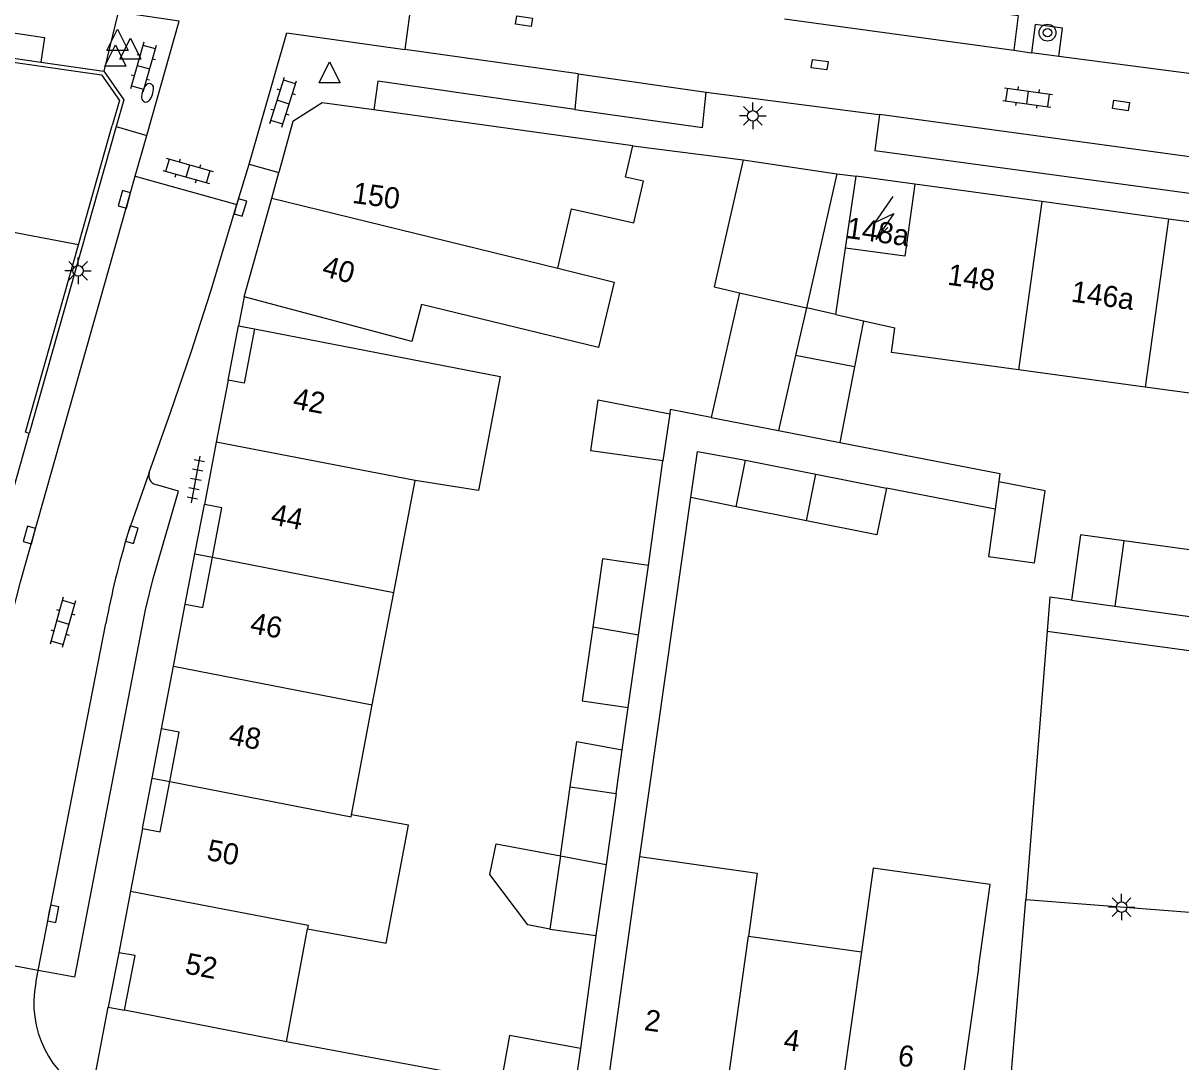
# Model space of a CAD drawing. Extents: x 132998 to 136004, y 396998 to 398512.
# Drawn here: x 133682.3 to 133737.1, y 397708.1 to 397757.2 of the extents above; entities that cross this region are included whole.
import ezdxf

# ---------------------------------------------------------------- set-up
doc = ezdxf.new("R2010")
doc.units = 0
for name, color, linetype in [('gg-afsc-erfafscheiding', 7, 'Continuous'), ('gg-afsc-muur', 7, 'Continuous'), ('gg-anno-huisnummerreeks BGT', 7, 'Continuous'), ('gg-bbg-bijgebouw', 7, 'Continuous'), ('gg-bbg-gedigitaliseerde bebouwing', 7, 'Continuous'), ('gg-bbg-gedigitaliseerde bijgebouw', 7, 'Continuous'), ('gg-bbg-hoofdgebouw', 7, 'Continuous'), ('gg-bbg-luifel en loopbrug', 7, 'Continuous'), ('gg-bbg-onder overbouw', 7, 'Continuous'), ('gg-bbg-pand overbouw', 7, 'Continuous'), ('gg-bbg-tussenscheiding', 7, 'Continuous'), ('gg-bbg-tussenscheiding niveau 01', 7, 'Continuous'), ('gg-knt-verharding', 7, 'Continuous'), ('gg-knt-verharding nz', 7, 'Continuous'), ('gt-grn-vlakafsluiter', 7, 'Continuous'), ('gt-grn-weggrens', 7, 'Continuous'), ('gt-symb-boom', 7, 'Continuous'), ('gt-symb-brandkraan', 7, 'Continuous'), ('gt-symb-klinker verharding', 7, 'Continuous'), ('gt-symb-kolk', 7, 'Continuous'), ('gt-symb-kolk center center', 7, 'Continuous'), ('gt-symb-lichtmast', 7, 'Continuous'), ('gt-symb-tegel verharding', 7, 'Continuous'), ('gt-symb-trafo symbool', 7, 'Continuous'), ('gt-symb-waterafsluiter', 7, 'Continuous')]:
    doc.layers.add(name, color=color, linetype=linetype)

# ---------------------------------------------------------------- blocks, each defined once
blk = doc.blocks.new('gt0-KOLKCC')
at = {"layer": 'gt-symb-kolk center center'}
blk.add_lwpolyline([(-0.375, 0.2), (0.375, 0.2), (0.375, -0.2), (-0.375, -0.2)], close=True, dxfattribs=at)
blk = doc.blocks.new('gt0-WAFSL')
at = {"layer": 'gt-symb-waterafsluiter'}
for p, q in [((-0.5, -0.333), (0, 0.667)), ((0, 0.667), (0.5, -0.333)), ((0.5, -0.333), (-0.5, -0.333))]:
    blk.add_line(p, q, dxfattribs=at)
blk = doc.blocks.new('gt0-BOOM')
at = {"layer": 'gt-symb-boom'}
for radius in [0.4, 0.2]:
    blk.add_circle((0, 0), radius, dxfattribs=at)
blk = doc.blocks.new('gt0-KL1')
at = {"layer": 'gt-symb-klinker verharding'}
for p, q in [((-1.15, 0.3), (1.15, 0.3)), ((-1, -0.3), (-1, 0.3)), ((-0.5, 0.3), (-0.5, 0.45)), ((0, -0.3), (0, 0.3)), ((0.5, 0.3), (0.5, 0.45)), ((1, -0.3), (1, 0.3)), ((-1.15, -0.3), (1.15, -0.3)), ((-0.5, -0.45), (-0.5, -0.3)), ((0.5, -0.45), (0.5, -0.3))]:
    blk.add_line(p, q, dxfattribs=at)
blk = doc.blocks.new('gt0-HSP')
at = {"layer": 'gt-symb-trafo symbool'}
for points in [[(0.771, 0.746), (-0.529, -0.004), (0.471, -0.004), (-0.829, -0.754)], [(-0.217, -0.24), (-0.829, -0.754), (-0.077, -0.48)]]:
    blk.add_lwpolyline(points, dxfattribs=at)
blk = doc.blocks.new('gt0-LMAST')
at = {"layer": 'gt-symb-lichtmast'}
for p, q in [((-0.005, 0.246), (-0.005, 0.621)), ((-0.182, 0.173), (-0.447, 0.438)), ((0.172, 0.173), (0.437, 0.438)), ((-0.255, -0.004), (-0.63, -0.004)), ((-0.182, -0.181), (-0.447, -0.446)), ((-0.005, -0.254), (-0.005, -0.629)), ((0.437, -0.446), (0.172, -0.181)), ((0.245, -0.004), (0.62, -0.004))]:
    blk.add_line(p, q, dxfattribs=at)
blk.add_circle((-0.005, -0.004), 0.25, dxfattribs=at)
blk = doc.blocks.new('gt0-TEG1')
at = {"layer": 'gt-symb-tegel verharding'}
for p, q in [((-1.125, 0), (1.125, 0)), ((-0.9, -0.25), (-0.9, 0.25)), ((-0.45, -0.25), (-0.45, 0.25)), ((0, -0.25), (0, 0.25)), ((0.45, -0.25), (0.45, 0.25)), ((0.9, -0.25), (0.9, 0.25))]:
    blk.add_line(p, q, dxfattribs=at)
blk = doc.blocks.new('gt0-KOLK')
at = {"layer": 'gt-symb-kolk'}
blk.add_lwpolyline([(0, 0), (0.375, 0), (0.375, 0.4), (-0.375, 0.4), (-0.375, 0), (0, 0)], dxfattribs=at)
blk = doc.blocks.new('gt0-BR')
at = {"layer": 'gt-symb-brandkraan'}
for centre, radius, start, end in [((-0.244, 0), 0.206, 107.5669, 252.4331), ((0.599, -2.664), 3, 106.892, 107.5669), ((0, -0.691), 0.938, 73.108, 106.892), ((-0.599, -2.664), 3, 72.4331, 73.108), ((0.244, 0), 0.206, 287.567, 72.4331), ((0.599, 2.664), 3, 252.4331, 253.108), ((0, 0.691), 0.938, 253.108, 286.8921), ((-0.599, 2.664), 3, 286.8921, 287.567)]:
    blk.add_arc(centre, radius, start, end, dxfattribs=at)

msp = doc.modelspace()

# ---------------------------------------------------------------- linework, layer by layer
at = {"layer": 'gg-afsc-erfafscheiding'}
for p, q in [((133711.9, 397731.56), (133712.583, 397736.511)), ((133728.308, 397734.226), (133723.163, 397735.216)), ((133711.488, 397717.776), (133713.911, 397734.767)), ((133710.656, 397722.833), (133710.936, 397724.836)), ((133709.409, 397714.035), (133708.678, 397708.691))]:
    msp.add_line(p, q, dxfattribs=at)
for points in [[(133714.872, 397738.56), (133712.926, 397738.938), (133712.904, 397738.728)], [(133720.956, 397737.38), (133728.538, 397735.909), (133728.484, 397735.513)]]:
    msp.add_lwpolyline(points, dxfattribs=at)
at = {"layer": 'gg-afsc-muur'}
for p, q in [((133644.119, 397761), (133683.118, 397755.381)), ((133683.118, 397755.381), (133686.11, 397754.95)), ((133686.692, 397752.337), (133682.576, 397737.809)), ((133684.905, 397746.728), (133686.509, 397752.389)), ((133730.773, 397728.45), (133729.77, 397715.74)), ((133704.92, 397707.118), (133694.756, 397709.017))]:
    msp.add_line(p, q, dxfattribs=at)
for points in [[(133673.543, 397756.569), (133686.001, 397754.774), (133686.843, 397753.565), (133686.509, 397752.389)], [(133686.11, 397754.95), (133687.05, 397753.6), (133686.692, 397752.337)], [(133682.576, 397737.809), (133682.393, 397737.861), (133684.905, 397746.728)]]:
    msp.add_lwpolyline(points, dxfattribs=at)
at = {"layer": 'gg-bbg-bijgebouw'}
for p, q in [((133716.38, 397750.76), (133720.81, 397750.09)), ((133731.93, 397729.91), (133733.985, 397729.63)), ((133733.985, 397729.63), (133739.06, 397728.94)), ((133710.367, 397720.762), (133709.889, 397717.403)), ((133709.889, 397717.403), (133709.409, 397714.035)), ((133708.678, 397708.691), (133708.371, 397706.615))]:
    msp.add_line(p, q, dxfattribs=at)
for points in [[(133734.413, 397732.719), (133732.35, 397733), (133731.93, 397729.91)], [(133739.06, 397728.94), (133739.48, 397732.03), (133734.413, 397732.719)]]:
    msp.add_lwpolyline(points, dxfattribs=at)
at = {"layer": 'gg-bbg-gedigitaliseerde bebouwing'}
for p, q in [((133710.815, 397749.942), (133711.15, 397751.42)), ((133721.233, 397746.583), (133721.729, 397749.98)), ((133720.773, 397743.432), (133721.233, 397746.583)), ((133707.613, 397745.626), (133710.27, 397744.971)), ((133720.773, 397743.432), (133722.078, 397743.137)), ((133722.078, 397743.137), (133723.561, 397742.8)), ((133735.422, 397739.994), (133729.413, 397740.818)), ((133741.432, 397739.17), (133735.422, 397739.994)), ((133699.834, 397730.271), (133700.846, 397735.583)), ((133698.821, 397724.956), (133699.834, 397730.271)), ((133697.83, 397719.754), (133698.821, 397724.956)), ((133700.533, 397719.261), (133697.83, 397719.754)), ((133728.832, 397704.584), (133729.77, 397715.74)), ((133716.629, 397714.019), (133721.983, 397713.27)), ((133727.526, 397712.494), (133726.455, 397704.915))]:
    msp.add_line(p, q, dxfattribs=at)
for points in [[(133707.613, 397745.626), (133708.252, 397748.442), (133711.207, 397747.772), (133711.655, 397749.752), (133710.815, 397749.942)], [(133710.27, 397744.971), (133709.524, 397741.874), (133701.157, 397743.914), (133700.699, 397742.164), (133692.76, 397744.27)], [(133729.413, 397740.818), (133723.4, 397741.643), (133723.561, 397742.8)], [(133693.243, 397742.756), (133704.882, 397740.498), (133703.846, 397735.105), (133700.846, 397735.583)], [(133711.488, 397717.776), (133717.046, 397716.999), (133716.629, 397714.019)], [(133727.526, 397712.494), (133728.078, 397716.456), (133722.535, 397717.228), (133721.983, 397713.27)]]:
    msp.add_lwpolyline(points, dxfattribs=at)
at = {"layer": 'gg-bbg-gedigitaliseerde bijgebouw'}
for p, q in [((133720.81, 397750.09), (133719.373, 397743.75)), ((133716.211, 397744.467), (133714.872, 397738.56)), ((133719.373, 397743.75), (133718.862, 397741.498)), ((133721.653, 397740.954), (133718.862, 397741.498)), ((133721.653, 397740.954), (133720.956, 397737.38)), ((133712.904, 397738.728), (133712.583, 397736.511)), ((133714.872, 397738.56), (133718.056, 397737.943)), ((133718.056, 397737.943), (133720.956, 397737.38)), ((133716.05, 397734.34), (133716.492, 397736.544)), ((133716.492, 397736.544), (133719.826, 397735.88)), ((133719.826, 397735.88), (133723.163, 397735.216)), ((133728.484, 397735.513), (133728.308, 397734.226)), ((133719.379, 397733.676), (133716.05, 397734.34)), ((133711.427, 397728.264), (133711.9, 397731.56)), ((133710.936, 397724.836), (133711.427, 397728.264)), ((133707.727, 397717.808), (133708.192, 397721.072)), ((133708.192, 397721.072), (133710.367, 397720.762)), ((133707.727, 397717.808), (133707.234, 397714.345)), ((133707.234, 397714.345), (133709.409, 397714.035))]:
    msp.add_line(p, q, dxfattribs=at)
for points in [[(133716.38, 397750.76), (133715.015, 397744.738), (133716.211, 397744.467)], [(133712.583, 397736.511), (133709.169, 397736.98), (133709.517, 397739.392), (133712.904, 397738.728)], [(133723.163, 397735.216), (133722.711, 397733.012), (133719.379, 397733.676)], [(133728.308, 397734.226), (133728, 397731.979), (133730.178, 397731.681), (133730.683, 397735.091), (133728.484, 397735.513)], [(133711.9, 397731.56), (133709.717, 397731.872), (133709.256, 397728.64)], [(133709.256, 397728.64), (133708.758, 397725.146), (133710.936, 397724.836)], [(133708.678, 397708.691), (133705.323, 397709.308), (133704.92, 397707.118)]]:
    msp.add_lwpolyline(points, dxfattribs=at)
at = {"layer": 'gg-bbg-hoofdgebouw'}
for p, q in [((133711.15, 397751.42), (133698.898, 397753.119)), ((133694.055, 397748.943), (133694.392, 397750.158)), ((133724.505, 397749.6), (133721.729, 397749.98)), ((133730.517, 397748.778), (133724.505, 397749.6)), ((133692.76, 397744.27), (133694.055, 397748.943)), ((133736.526, 397747.956), (133730.517, 397748.778)), ((133742.536, 397747.134), (133736.526, 397747.956)), ((133691.987, 397740.328), (133691.428, 397737.388)), ((133691.428, 397737.388), (133690.868, 397734.444)), ((133689.405, 397726.794), (133689.964, 397729.724)), ((133688.84, 397723.832), (133689.405, 397726.794)), ((133687.936, 397719.112), (133687.369, 397716.148)), ((133709.898, 397706.384), (133711.488, 397717.776)), ((133687.369, 397716.148), (133686.81, 397713.227)), ((133729.77, 397715.74), (133775.76, 397712.21)), ((133694.756, 397709.017), (133695.746, 397714.362)), ((133694.756, 397709.017), (133687.08, 397710.506))]:
    msp.add_line(p, q, dxfattribs=at)
for points in [[(133698.898, 397753.119), (133696.44, 397753.46), (133695.06, 397752.57), (133694.392, 397750.158)], [(133695.746, 397714.362), (133699.481, 397713.681), (133700.533, 397719.261)]]:
    msp.add_lwpolyline(points, dxfattribs=at)
at = {"layer": 'gg-bbg-luifel en loopbrug'}
for p, q in [((133720.81, 397750.09), (133721.729, 397749.98)), ((133720.773, 397743.432), (133719.373, 397743.75)), ((133722.078, 397743.137), (133721.653, 397740.954)), ((133716.05, 397734.34), (133713.911, 397734.767)), ((133710.367, 397720.762), (133710.656, 397722.833))]:
    msp.add_line(p, q, dxfattribs=at)
for points in [[(133713.911, 397734.767), (133714.224, 397736.958), (133716.492, 397736.544)], [(133708.192, 397721.072), (133708.498, 397723.221), (133710.656, 397722.833)], [(133707.234, 397714.345), (133706.189, 397714.542), (133704.384, 397716.926), (133704.678, 397718.379), (133707.727, 397717.808)]]:
    msp.add_lwpolyline(points, dxfattribs=at)
at = {"layer": 'gg-bbg-onder overbouw'}
for points in [[(133693.243, 397742.756), (133692.754, 397740.182), (133691.987, 397740.328)], [(133691.245, 397731.947), (133691.693, 397734.286), (133690.868, 397734.444)], [(133689.964, 397729.724), (133690.789, 397729.566), (133691.245, 397731.947)], [(133689.226, 397721.328), (133689.674, 397723.672), (133688.84, 397723.832)], [(133687.936, 397719.112), (133688.771, 397718.952), (133689.226, 397721.328)], [(133687.08, 397710.506), (133687.595, 397713.09), (133686.81, 397713.227)]]:
    msp.add_lwpolyline(points, dxfattribs=at)
at = {"layer": 'gg-bbg-pand overbouw'}
for p, q in [((133691.987, 397740.328), (133692.477, 397742.901)), ((133692.477, 397742.901), (133693.243, 397742.756)), ((133690.421, 397732.108), (133690.868, 397734.444)), ((133689.964, 397729.724), (133690.421, 397732.108)), ((133688.392, 397721.49), (133688.84, 397723.832)), ((133687.936, 397719.112), (133688.392, 397721.49)), ((133686.81, 397713.227), (133686.317, 397710.653)), ((133686.317, 397710.653), (133687.08, 397710.506))]:
    msp.add_line(p, q, dxfattribs=at)
at = {"layer": 'gg-bbg-tussenscheiding'}
for p, q in [((133694.055, 397748.943), (133707.613, 397745.626)), ((133730.517, 397748.778), (133729.413, 397740.818)), ((133736.526, 397747.956), (133735.422, 397739.994)), ((133716.211, 397744.467), (133719.373, 397743.75)), ((133718.862, 397741.498), (133718.056, 397737.943)), ((133700.846, 397735.583), (133691.428, 397737.388)), ((133719.379, 397733.676), (133719.826, 397735.88)), ((133734.413, 397732.719), (133733.985, 397729.63)), ((133691.245, 397731.947), (133699.834, 397730.271)), ((133711.427, 397728.264), (133709.256, 397728.64)), ((133689.405, 397726.794), (133698.821, 397724.956)), ((133707.727, 397717.808), (133709.889, 397717.403)), ((133715.549, 397706.349), (133716.629, 397714.019)), ((133721.983, 397713.27), (133720.771, 397704.766))]:
    msp.add_line(p, q, dxfattribs=at)
for points in [[(133724.505, 397749.6), (133724.033, 397746.2), (133721.233, 397746.583)], [(133689.226, 397721.328), (133697.812, 397719.661), (133697.83, 397719.754)], [(133687.369, 397716.148), (133695.778, 397714.537), (133695.746, 397714.362)]]:
    msp.add_lwpolyline(points, dxfattribs=at)
at = {"layer": 'gg-bbg-tussenscheiding niveau 01'}
for p, q in [((133690.421, 397732.108), (133691.245, 397731.947)), ((133688.392, 397721.49), (133689.226, 397721.328))]:
    msp.add_line(p, q, dxfattribs=at)
at = {"layer": 'gg-knt-verharding'}
for p, q in [((133700.929, 397760.146), (133700.366, 397755.987)), ((133708.568, 397754.82), (133700.366, 397755.987)), ((133729.194, 397755.942), (133730.039, 397755.826)), ((133731.329, 397755.656), (133730.039, 397755.826)), ((133746.202, 397753.697), (133731.329, 397755.656)), ((133699.074, 397754.474), (133698.898, 397753.119)), ((133708.403, 397753.147), (133699.074, 397754.474)), ((133708.568, 397754.82), (133708.403, 397753.147)), ((133714.626, 397753.959), (133722.673, 397752.922)), ((133722.673, 397752.922), (133722.833, 397752.9)), ((133686.692, 397752.337), (133688.136, 397751.91)), ((133687.594, 397749.991), (133688.136, 397751.91)), ((133711.15, 397751.42), (133716.38, 397750.76)), ((133692.403, 397748.637), (133692.982, 397750.557)), ((133692.982, 397750.557), (133694.392, 397750.158)), ((133687.594, 397749.991), (133692.403, 397748.637)), ((133689.64, 397735.078), (133688.55, 397735.389)), ((133682.996, 397712.391), (133678.585, 397713.214)), ((133682.88, 397711.799), (133682.996, 397712.391)), ((133684.736, 397712.067), (133682.996, 397712.391))]:
    msp.add_line(p, q, dxfattribs=at)
for points in [[(133718.581, 397759.065), (133729.408, 397757.596), (133729.194, 397755.942)], [(133731.329, 397755.656), (133731.508, 397756.994), (133730.213, 397757.163), (133730.039, 397755.826)], [(133684.905, 397746.728), (133673.183, 397748.965), (133673.543, 397756.569)], [(133708.403, 397753.147), (133714.461, 397752.285), (133714.626, 397753.959)], [(133722.833, 397752.9), (133722.615, 397751.194), (133748.241, 397747.723), (133748.525, 397749.406)], [(133678.585, 397713.214), (133681.024, 397725.93), (133681.543, 397728.369), (133682.165, 397730.783), (133687.594, 397749.991)], [(133688.252, 397735.95), (133689.261, 397738.801), (133690.244, 397741.652), (133691.156, 397744.499), (133692.403, 397748.637)], [(133730.773, 397728.45), (133753.19, 397725.41), (133755.882, 397745.307)], [(133684.736, 397712.067), (133688.084, 397729.459), (133688.444, 397730.938), (133689.64, 397735.078)], [(133731.93, 397729.91), (133730.9, 397730.05), (133730.773, 397728.45)]]:
    msp.add_lwpolyline(points, dxfattribs=at)
for centre, radius, start, end in [((133688.676, 397735.815), 0.445, 162.3722, 253.5818), ((133687.705, 397710.856), 4.916, 168.9408, 243.5356)]:
    msp.add_arc(centre, radius, start, end, dxfattribs=at)
at = {"layer": 'gg-knt-verharding nz'}
for p, q in [((133718.34, 397757.436), (133729.194, 397755.942)), ((133692.982, 397750.557), (133694.775, 397756.765)), ((133694.775, 397756.765), (133700.366, 397755.987)), ((133708.568, 397754.82), (133714.626, 397753.959)), ((133748.525, 397749.406), (133722.833, 397752.9)), ((133688.252, 397735.95), (133687.247, 397733.074)), ((133682.996, 397712.391), (133686.205, 397728.803))]:
    msp.add_line(p, q, dxfattribs=at)
msp.add_lwpolyline([(133688.136, 397751.91), (133689.681, 397757.326), (133686.792, 397757.752)], dxfattribs=at)
msp.add_arc((133725.328, 397721.521), 39.795, 163.1229, 169.4558, dxfattribs=at)
at = {"layer": 'gt-grn-vlakafsluiter'}
msp.add_line((133692.76, 397744.27), (133692.477, 397742.901), dxfattribs=at)
at = {"layer": 'gt-grn-weggrens'}
for p, q in [((133686.792, 397757.752), (133686.11, 397754.95)), ((133681.717, 397734.779), (133682.576, 397737.809)), ((133685.514, 397706.455), (133686.317, 397710.653))]:
    msp.add_line(p, q, dxfattribs=at)
msp.add_lwpolyline([(133674.769, 397757.827), (133683.3, 397756.54), (133683.118, 397755.381)], dxfattribs=at)

# ---------------------------------------------------------------- block references
at = {"layer": 'gt-symb-boom'}
msp.add_blockref('gt0-BOOM', (133730.794, 397756.776), dxfattribs=at)
at = {"layer": 'gt-symb-brandkraan', "rotation": 71.76430853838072}
msp.add_blockref('gt0-BR', (133688.179, 397753.928), dxfattribs=at)
at = {"layer": 'gt-symb-klinker verharding'}
for p, rotation in [((133687.976, 397755.143), -105.89818708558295), ((133694.6, 397753.489), 72.54344186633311), ((133729.856, 397753.71), -7.935550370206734), ((133690.091, 397750.233), -15.717252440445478), ((133684.164, 397728.865), -105.71725243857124)]:
    msp.add_blockref('gt0-KL1', p, dxfattribs=dict(at, rotation=rotation))
at = {"layer": 'gt-symb-kolk'}
for p, rotation in [((133687.275, 397748.829), 74.21205294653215), ((133692.38, 397748.558), -106.77344650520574), ((133682.777, 397732.945), 74.21205294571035), ((133687.247, 397733.074), -107.03953512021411), ((133683.508, 397715.103), -101.13011108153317)]:
    msp.add_blockref('gt0-KOLK', p, dxfattribs=dict(at, rotation=rotation))
at = {"layer": 'gt-symb-kolk center center'}
for p, rotation in [((133706, 397757.318), -8.146080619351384), ((133720.005, 397755.265), -7.4202754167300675), ((133734.27, 397753.334), -8.219120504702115)]:
    msp.add_blockref('gt0-KOLKCC', p, dxfattribs=dict(at, rotation=rotation))
at = {"layer": 'gt-symb-lichtmast'}
for p in [(133716.843, 397752.842), (133684.892, 397745.506), (133734.307, 397715.392)]:
    msp.add_blockref('gt0-LMAST', p, dxfattribs=at)
at = {"layer": 'gt-symb-tegel verharding', "rotation": 79.21838326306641}
msp.add_blockref('gt0-TEG1', (133690.463, 397735.631), dxfattribs=at)
at = {"layer": 'gt-symb-trafo symbool', "rotation": 25.411600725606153}
msp.add_blockref('gt0-HSP', (133723.09, 397748.022), dxfattribs=at)
at = {"layer": 'gt-symb-waterafsluiter'}
for p in [(133686.756, 397756.272), (133687.366, 397755.85), (133686.655, 397755.528), (133696.799, 397754.73)]:
    msp.add_blockref('gt0-WAFSL', p, dxfattribs=at)

# ---------------------------------------------------------------- texts
at = {"layer": 'gg-anno-huisnummerreeks BGT'}
for s, rotation, p in [('150', 352.1, (133697.838, 397748.723)), ('148a', 352.2, (133721.223, 397747.065)), ('40', 344.5, (133696.385, 397745.281)), ('148', 352.2, (133726.022, 397744.851)), ('146a', 352.2, (133731.875, 397744.051)), ('42', 349.2, (133695.015, 397739.002)), ('44', 349.2, (133693.971, 397733.513)), ('46', 349.2, (133692.987, 397728.37)), ('48', 349.2, (133691.982, 397723.104)), ('50', 349.2, (133690.934, 397717.628)), ('52', 349.2, (133689.905, 397712.253)), ('2', 352, (133711.661, 397709.569)), ('4', 352.1, (133718.259, 397708.649)), ('6', 352.1, (133723.669, 397707.897))]:
    msp.add_text(s, height=1, rotation=rotation, dxfattribs=at).set_placement(p)

doc.saveas('drawing.dxf')
